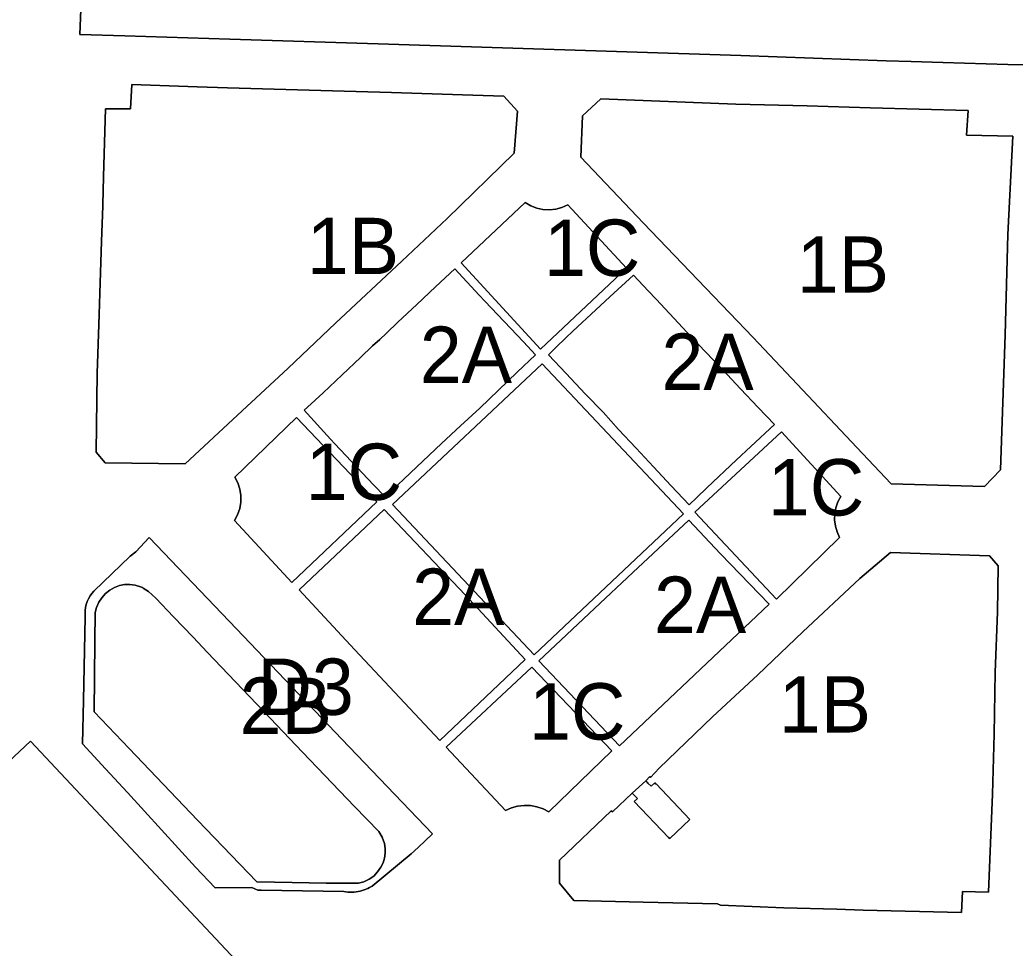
# Model space of a CAD drawing. Extents: x 598968 to 613553, y 4409678 to 4430833.
# Drawn here: x 607397.8 to 607609.6, y 4415075.5 to 4415273.1 of the extents above; entities that cross this region are included whole.
import ezdxf

# ---------------------------------------------------------------- set-up
doc = ezdxf.new("R2010")
doc.units = 0
for name, color, linetype in [('1', 7, 'Continuous'), ('ZONA 1B. Illes de cases extensives - ANNEX III C', 7, 'Continuous'), ('ZONA 1C. Cases aïllades centrals - ANNEX III C', 7, 'Continuous'), ('ZONA 2A. Fileres de cases - ANNEX III C', 7, 'Continuous'), ('ZONA 2B. Blocs aïllats - ANNEX III C', 7, 'Continuous'), ('ZONES URBANES. Espai lliure privat', 7, 'Continuous')]:
    doc.layers.add(name, color=color, linetype=linetype)

msp = doc.modelspace()

# ---------------------------------------------------------------- linework, layer by layer
at = {"layer": '1'}
for points in [[(607611.3336, 4415263.5804), (607608.0558, 4415263.6576), (607594.2184, 4415264.0432), (607587.4797, 4415264.2428), (607582.1741, 4415264.3951), (607551.2448, 4415265.534), (607474.0118, 4415268.0475), (607442.4766, 4415269.0382), (607420.1369, 4415269.7206), (607410.5229, 4415270.0186), (607410.898, 4415278.9685)], [(607410.898, 4415278.9685), (607410.5229, 4415270.0186), (607420.1369, 4415269.7206), (607442.4766, 4415269.0382), (607474.0118, 4415268.0475), (607551.2448, 4415265.534), (607582.1741, 4415264.3951), (607587.4797, 4415264.2428), (607594.2184, 4415264.0432), (607608.0558, 4415263.6576), (607611.3336, 4415263.5804), (607622.943, 4415263.3067), (607622.3131, 4415255.9868), (607622.8407, 4415255.9718), (607622.8617, 4415255.9712), (607647.4966, 4415255.2678), (607658.7094, 4415254.9477), (607666.8208, 4415254.7342), (607667.1204, 4415264.2254), (607667.3182, 4415270.4899), (607667.4999, 4415276.2469)]]:
    msp.add_lwpolyline(points, dxfattribs=at)
for points in [[(607435.5198, 4415258.8828), (607441.9896, 4415258.6528), (607441.9898, 4415258.662), (607464.3096, 4415257.9884), (607476.8744, 4415257.6636), (607492.0193, 4415257.1889), (607500.7892, 4415256.919), (607503.7091, 4415253.6591), (607503.0192, 4415244.7492), (607488.7344, 4415230.8591), (607479.0696, 4415221.769), (607464.9298, 4415208.5289), (607454.8863, 4415199.0005), (607444.13, 4415188.9488), (607432.9602, 4415178.6187), (607415.9204, 4415178.8384), (607414.0304, 4415181.1083), (607414.1503, 4415192.2882), (607414.2603, 4415197.9181), (607414.3703, 4415201.9881), (607414.6403, 4415210.378), (607414.7702, 4415214.9479), (607415.1202, 4415225.9578), (607415.4202, 4415233.5277), (607415.4201, 4415233.72), (607415.5901, 4415239.7577), (607415.9901, 4415254.2175), (607421.3, 4415254.1676), (607421.61, 4415259.3576)], [(607606.4782, 4415177.3419), (607603.0882, 4415173.7619), (607583.2085, 4415174.3515), (607575.9385, 4415182.0613), (607563.2186, 4415195.5609), (607553.8687, 4415205.4906), (607543.8062, 4415215.9717), (607530.4289, 4415229.8999), (607517.189, 4415243.8795), (607517.509, 4415252.7094), (607521.4473, 4415256.2991), (607550.1886, 4415255.1605), (607565.3184, 4415254.8602), (607578.7682, 4415254.4205), (607599.628, 4415253.8009), (607599.258, 4415248.6009), (607609.1079, 4415248.4011), (607608.088, 4415227.4213), (607607.4681, 4415206.0316)], [(607509.1168, 4415232.7569), (607510.4761, 4415232.6832), (607511.8302, 4415232.8239), (607513.1454, 4415233.1756), (607514.3891, 4415233.7296), (607526.919, 4415220.2299), (607508.6193, 4415202.9998), (607491.7215, 4415221.403), (607505.3401, 4415234.2203), (607506.5165, 4415233.5351), (607507.7859, 4415233.0432)], [(607479.5897, 4415175.3996), (607475.5098, 4415171.5396), (607473.0104, 4415174.1262), (607464.8035, 4415182.8902), (607463.9139, 4415183.8399), (607458.2598, 4415189.999), (607459.7899, 4415191.389), (607462.2999, 4415193.7291), (607466.3698, 4415197.5784), (607470.2497, 4415201.2491), (607472.8569, 4415203.7032), (607474.3648, 4415205.0853), (607475.8096, 4415206.4292), (607478.2496, 4415208.7492), (607482.2595, 4415212.5342), (607486.2695, 4415216.2792), (607490.3492, 4415220.1078), (607495.5594, 4415214.5294), (607496.7566, 4415213.2634), (607504.9993, 4415204.5397), (607507.5393, 4415201.8098), (607503.6393, 4415198.0898), (607499.6494, 4415194.2697), (607495.6595, 4415190.4697), (607491.5495, 4415186.6897), (607487.5396, 4415182.8996), (607483.5596, 4415179.1496)], [(607541.8343, 4415171.4398), (607540.199, 4415169.8908), (607536.419, 4415173.9207), (607532.6291, 4415177.9505), (607528.9191, 4415181.9204), (607525.1691, 4415185.9103), (607521.9292, 4415189.5902), (607518.0711, 4415193.4984), (607514.0292, 4415197.81), (607510.2692, 4415201.8198), (607511.8424, 4415203.3382), (607513.9992, 4415205.4199), (607515.5006, 4415206.8299), (607520.3791, 4415211.4099), (607523.3489, 4415214.1858), (607528.359, 4415218.78), (607531.5082, 4415215.4278), (607533.1898, 4415213.6393), (607536.0656, 4415210.5756), (607539.8309, 4415206.5799), (607543.6288, 4415202.5355), (607547.3711, 4415198.5879), (607551.1564, 4415194.5837), (607554.9461, 4415190.5909), (607558.3987, 4415186.9509), (607553.358, 4415182.2713), (607550.3244, 4415179.4216), (607543.9889, 4415173.4808)], [(607538.9907, 4415167.9746), (607507.2504, 4415137.9118), (607477.0567, 4415169.912), (607508.9508, 4415199.9041)], [(607538.9907, 4415167.9746), (607508.9508, 4415199.9041), (607477.0567, 4415169.912), (607507.2504, 4415137.9118)], [(607473.7531, 4415170.5019), (607455.66, 4415153.3594), (607443.4701, 4415166.499), (607444.1285, 4415167.7325), (607444.5812, 4415169.0554), (607444.8165, 4415170.4337), (607444.8285, 4415171.8318), (607444.6169, 4415173.2139), (607444.1871, 4415174.5443), (607443.55, 4415175.7889), (607456.6498, 4415188.449)], [(607572.2586, 4415162.9014), (607558.7888, 4415149.8113), (607541.449, 4415168.2808), (607559.8687, 4415185.391), (607572.5186, 4415171.6613), (607571.902, 4415170.5025), (607571.4694, 4415169.2632), (607571.2308, 4415167.9724), (607571.1919, 4415166.6603), (607571.3535, 4415165.3576), (607571.7118, 4415164.0948)], [(607505.3095, 4415136.9205), (607487.1555, 4415119.7133), (607469.02, 4415139.0698), (607457.2061, 4415151.7545), (607475.2898, 4415168.8596), (607492.5653, 4415150.7299)], [(607557.2589, 4415148.7113), (607525.3938, 4415118.5673), (607508.2295, 4415136.6506), (607520.0993, 4415147.7807), (607528.2592, 4415155.4307), (607540.169, 4415166.6108), (607546.899, 4415159.421)], [(607425.3178, 4415162.8913), (607443.8875, 4415143.4525), (607449.7074, 4415137.3529), (607458.7472, 4415127.8935), (607460.6173, 4415125.9336), (607466.3173, 4415119.9739), (607485.5769, 4415099.8051), (607482.5371, 4415096.9151), (607481.0671, 4415095.5251), (607472.7273, 4415088.6449), (607472.2273, 4415088.3649), (607471.8373, 4415088.1749), (607471.0274, 4415087.8549), (607470.6174, 4415087.7249), (607470.1974, 4415087.6149), (607469.7674, 4415087.5249), (607469.3374, 4415087.4548), (607468.9074, 4415087.4148), (607468.4775, 4415087.3848), (607468.0375, 4415087.3847), (607467.6075, 4415087.4047), (607467.1775, 4415087.4447), (607466.7475, 4415087.5147), (607449.1478, 4415087.8341), (607448.4278, 4415087.8441), (607447.1278, 4415088.3539), (607439.358, 4415088.3437), (607435.1481, 4415092.6835), (607420.6684, 4415108.5925), (607416.0284, 4415113.6423), (607411.1085, 4415118.9819), (607411.3184, 4415128.1917), (607411.7082, 4415146.0313), (607411.6482, 4415146.6913), (607411.6682, 4415147.3513), (607411.7482, 4415148.0113), (607411.8982, 4415148.6513), (607412.1082, 4415149.2812), (607412.3782, 4415149.8812), (607412.7082, 4415150.4612), (607413.0882, 4415150.9912), (607413.5282, 4415151.4912), (607421.238, 4415158.9313), (607422.4279, 4415159.8613)], [(607530.99, 4415111.1115), (607531.8696, 4415111.9911), (607532.0193, 4415111.8413), (607533.8793, 4415113.7814), (607545.1791, 4415124.7614), (607554.829, 4415133.7015), (607564.3989, 4415142.829), (607576.5218, 4415154.1789), (607583.0785, 4415159.7017), (607604.1483, 4415159.0421), (607606.0183, 4415156.9021), (607605.8383, 4415146.9922), (607605.3627, 4415134.23), (607605.1584, 4415121.0626), (607604.7984, 4415108.2927), (607603.9585, 4415087.363), (607598.3975, 4415087.5292), (607598.2086, 4415083.0529), (607577.2589, 4415083.5725), (607571.6689, 4415083.7424), (607560.3891, 4415084.0722), (607546.8892, 4415084.6019), (607546.2692, 4415084.8919), (607530.4294, 4415085.2916), (607515.7096, 4415085.6313), (607512.6196, 4415089.3312), (607512.6596, 4415094.1712), (607523.6594, 4415104.7013), (607523.8794, 4415104.4713), (607528.1094, 4415108.5013)], [(607523.7816, 4415117.4735), (607510.3696, 4415104.481), (607509.1421, 4415105.1196), (607507.833, 4415105.5673), (607506.4716, 4415105.8141), (607505.0886, 4415105.8545), (607503.7152, 4415105.6874), (607502.3822, 4415105.3168), (607501.1197, 4415104.7509), (607488.4998, 4415118.2805), (607506.7795, 4415135.2906)], [(607406.2436, 4415028.3837), (607357.7665, 4415079.882), (607400.0659, 4415119.5323), (607448.0291, 4415068.3834), (607494.246, 4415066.8294), (607500.435, 4415062.8748), (607499.825, 4415051.5949), (607498.0651, 4415043.685), (607491.9652, 4415032.845), (607490.0452, 4415030.475), (607482.0353, 4415016.935), (607480.3354, 4415012.755), (607477.1754, 4415002.7051), (607475.9355, 4414997.5151), (607474.8055, 4414990.8552), (607474.0155, 4414988.7052), (607472.5456, 4414987.3552), (607471.0256, 4414986.6852), (607467.1856, 4414986.4151), (607404.8763, 4414988.4539)], [(607448.0291, 4415068.3834), (607400.0659, 4415119.5323), (607357.7665, 4415079.882), (607406.2436, 4415028.3837), (607406.4361, 4415034.0034), (607442.4385, 4415068.5714)], [(607528.1094, 4415108.5013), (607529.2338, 4415107.3272), (607528.5594, 4415106.6813), (607535.8093, 4415099.0516), (607536.1044, 4415098.7951), (607540.3843, 4415102.8651), (607533.1844, 4415110.4349), (607533.1576, 4415110.4091), (607532.8893, 4415110.6914), (607532.1327, 4415109.9639), (607532.1093, 4415109.9414), (607531.4569, 4415110.6234), (607531.2587, 4415110.8306), (607530.99, 4415111.1115)]]:
    msp.add_lwpolyline(points, close=True, dxfattribs=at)
at = {"layer": 'ZONA 1B. Illes de cases extensives - ANNEX III C'}
for points in [[(607435.5198, 4415258.8828), (607421.61, 4415259.3576), (607421.3, 4415254.1676), (607415.9901, 4415254.2175), (607415.5901, 4415239.7577), (607415.4201, 4415233.72), (607415.4202, 4415233.5277), (607415.1202, 4415225.9578), (607414.7702, 4415214.9479), (607414.6403, 4415210.378), (607414.3703, 4415201.9881), (607414.2603, 4415197.9181), (607414.1503, 4415192.2882), (607414.0304, 4415181.1083), (607415.9204, 4415178.8384), (607432.9602, 4415178.6187), (607444.13, 4415188.9488), (607454.8863, 4415199.0005), (607464.9298, 4415208.5289), (607479.0696, 4415221.769), (607488.7344, 4415230.8591), (607503.0192, 4415244.7492), (607503.7091, 4415253.6591), (607500.7892, 4415256.919), (607492.0193, 4415257.1889), (607476.8744, 4415257.6636), (607464.3096, 4415257.9884), (607441.9898, 4415258.662), (607441.9896, 4415258.6528)], [(607606.4782, 4415177.3419), (607607.4681, 4415206.0316), (607608.088, 4415227.4213), (607609.1079, 4415248.4011), (607599.258, 4415248.6009), (607599.628, 4415253.8009), (607578.7682, 4415254.4205), (607565.3184, 4415254.8602), (607550.1886, 4415255.1605), (607521.4473, 4415256.2991), (607517.509, 4415252.7094), (607517.189, 4415243.8795), (607530.4289, 4415229.8999), (607543.8062, 4415215.9717), (607553.8687, 4415205.4906), (607563.2186, 4415195.5609), (607575.9385, 4415182.0613), (607583.2085, 4415174.3515), (607603.0882, 4415173.7619)], [(607528.1094, 4415108.5013), (607523.8794, 4415104.4713), (607523.6594, 4415104.7013), (607512.6596, 4415094.1712), (607512.6196, 4415089.3312), (607515.7096, 4415085.6313), (607530.4294, 4415085.2916), (607546.2692, 4415084.8919), (607546.8892, 4415084.6019), (607560.3891, 4415084.0722), (607571.6689, 4415083.7424), (607577.2589, 4415083.5725), (607598.2086, 4415083.0529), (607598.3975, 4415087.5292), (607603.9585, 4415087.363), (607604.7984, 4415108.2927), (607605.1584, 4415121.0626), (607605.3627, 4415134.23), (607605.8383, 4415146.9922), (607606.0183, 4415156.9021), (607604.1483, 4415159.0421), (607583.0785, 4415159.7017), (607576.5218, 4415154.1789), (607564.3989, 4415142.829), (607554.829, 4415133.7015), (607545.1791, 4415124.7614), (607533.8793, 4415113.7814), (607532.0193, 4415111.8413), (607531.8696, 4415111.9911), (607530.99, 4415111.1115), (607531.2587, 4415110.8306), (607531.4569, 4415110.6234), (607532.1093, 4415109.9414), (607532.1327, 4415109.9639), (607532.8893, 4415110.6914), (607533.1576, 4415110.4091), (607533.1844, 4415110.4349), (607540.3843, 4415102.8651), (607536.1044, 4415098.7951), (607535.8093, 4415099.0516), (607528.5594, 4415106.6813), (607529.2338, 4415107.3272)]]:
    msp.add_lwpolyline(points, close=True, dxfattribs=at)
at = {"layer": 'ZONA 1C. Cases aïllades centrals - ANNEX III C'}
for points in [[(607509.1168, 4415232.7569), (607507.7859, 4415233.0432), (607506.5165, 4415233.5351), (607505.3401, 4415234.2203), (607491.7215, 4415221.403), (607508.6193, 4415202.9998), (607526.919, 4415220.2299), (607514.3891, 4415233.7296), (607513.1454, 4415233.1756), (607511.8302, 4415232.8239), (607510.4761, 4415232.6832)], [(607473.7531, 4415170.5019), (607456.6498, 4415188.449), (607443.55, 4415175.7889), (607444.1871, 4415174.5443), (607444.6169, 4415173.2139), (607444.8285, 4415171.8318), (607444.8165, 4415170.4337), (607444.5812, 4415169.0554), (607444.1285, 4415167.7325), (607443.4701, 4415166.499), (607455.66, 4415153.3594)], [(607572.2586, 4415162.9014), (607571.7118, 4415164.0948), (607571.3535, 4415165.3576), (607571.1919, 4415166.6603), (607571.2308, 4415167.9724), (607571.4694, 4415169.2632), (607571.902, 4415170.5025), (607572.5186, 4415171.6613), (607559.8687, 4415185.391), (607541.449, 4415168.2808), (607558.7888, 4415149.8113)], [(607523.7816, 4415117.4735), (607506.7795, 4415135.2906), (607488.4998, 4415118.2805), (607501.1197, 4415104.7509), (607502.3822, 4415105.3168), (607503.7152, 4415105.6874), (607505.0886, 4415105.8545), (607506.4716, 4415105.8141), (607507.833, 4415105.5673), (607509.1421, 4415105.1196), (607510.3696, 4415104.481)]]:
    msp.add_lwpolyline(points, close=True, dxfattribs=at)
at = {"layer": 'ZONA 2A. Fileres de cases - ANNEX III C'}
for points in [[(607479.5897, 4415175.3996), (607483.5596, 4415179.1496), (607487.5396, 4415182.8996), (607491.5495, 4415186.6897), (607495.6595, 4415190.4697), (607499.6494, 4415194.2697), (607503.6393, 4415198.0898), (607507.5393, 4415201.8098), (607504.9993, 4415204.5397), (607496.7566, 4415213.2634), (607495.5594, 4415214.5294), (607490.3492, 4415220.1078), (607486.2695, 4415216.2792), (607482.2595, 4415212.5342), (607478.2496, 4415208.7492), (607475.8096, 4415206.4292), (607474.3648, 4415205.0853), (607472.8569, 4415203.7032), (607470.2497, 4415201.2491), (607466.3698, 4415197.5784), (607462.2999, 4415193.7291), (607459.7899, 4415191.389), (607458.2598, 4415189.999), (607463.9139, 4415183.8399), (607464.8035, 4415182.8902), (607473.0104, 4415174.1262), (607475.5098, 4415171.5396)], [(607541.8343, 4415171.4398), (607543.9889, 4415173.4808), (607550.3244, 4415179.4216), (607553.358, 4415182.2713), (607558.3987, 4415186.9509), (607554.9461, 4415190.5909), (607551.1564, 4415194.5837), (607547.3711, 4415198.5879), (607543.6288, 4415202.5355), (607539.8309, 4415206.5799), (607536.0656, 4415210.5756), (607533.1898, 4415213.6393), (607531.5082, 4415215.4278), (607528.359, 4415218.78), (607523.3489, 4415214.1858), (607520.3791, 4415211.4099), (607515.5006, 4415206.8299), (607513.9992, 4415205.4199), (607511.8424, 4415203.3382), (607510.2692, 4415201.8198), (607514.0292, 4415197.81), (607518.0711, 4415193.4984), (607521.9292, 4415189.5902), (607525.1691, 4415185.9103), (607528.9191, 4415181.9204), (607532.6291, 4415177.9505), (607536.419, 4415173.9207), (607540.199, 4415169.8908)], [(607505.3095, 4415136.9205), (607492.5653, 4415150.7299), (607475.2898, 4415168.8596), (607457.2061, 4415151.7545), (607469.02, 4415139.0698), (607487.1555, 4415119.7133)], [(607557.2589, 4415148.7113), (607546.899, 4415159.421), (607540.169, 4415166.6108), (607528.2592, 4415155.4307), (607520.0993, 4415147.7807), (607508.2295, 4415136.6506), (607525.3938, 4415118.5673)]]:
    msp.add_lwpolyline(points, close=True, dxfattribs=at)
at = {"layer": 'ZONA 2B. Blocs aïllats - ANNEX III C'}
msp.add_lwpolyline([(607469.8401, 4415089.2805), (607471.0049, 4415089.6049), (607472.0964, 4415090.1253), (607473.0817, 4415090.8262), (607473.9315, 4415091.6865), (607474.6201, 4415092.6805), (607475.0715, 4415093.6287), (607475.3772, 4415094.6333), (607475.5306, 4415095.6722), (607475.5282, 4415096.7224), (607475.37, 4415097.7605), (607474.8551, 4415099.0782), (607474.16, 4415100.3104), (607468.9801, 4415105.6403), (607457.9301, 4415117.2199), (607449.6701, 4415125.8597), (607437.6102, 4415138.5092), (607434.631, 4415141.6792), (607430.4703, 4415145.989), (607426.7003, 4415149.9589), (607425.1903, 4415151.3989), (607424.0354, 4415152.1288), (607423.8484, 4415152.2655), (607423.6416, 4415152.3698), (607423.4204, 4415152.4388), (607422.3354, 4415152.7649), (607421.2119, 4415152.9119), (607420.0795, 4415152.876), (607418.9677, 4415152.6579), (607417.9054, 4415152.2637), (607416.8927, 4415151.6863), (607415.9852, 4415150.9546), (607415.2062, 4415150.0873), (607414.5756, 4415149.1068), (607414.1098, 4415148.0381), (607413.8205, 4415146.9087), (607413.7205, 4415140.7788), (607413.5906, 4415125.759), (607421.0205, 4415117.9992), (607435.6204, 4415102.7497), (607448.1903, 4415089.6201), (607455.7412, 4415089.484), (607462.9502, 4415089.2803)], close=True, dxfattribs=at)
at = {"layer": 'ZONES URBANES. Espai lliure privat'}
for points in [[(607425.3178, 4415162.8913), (607422.4279, 4415159.8613), (607421.238, 4415158.9313), (607413.5282, 4415151.4912), (607413.0882, 4415150.9912), (607412.7082, 4415150.4612), (607412.3782, 4415149.8812), (607412.1082, 4415149.2812), (607411.8982, 4415148.6513), (607411.7482, 4415148.0113), (607411.6682, 4415147.3513), (607411.6482, 4415146.6913), (607411.7082, 4415146.0313), (607411.3184, 4415128.1917), (607411.1085, 4415118.9819), (607416.0284, 4415113.6423), (607420.6684, 4415108.5925), (607435.1481, 4415092.6835), (607439.358, 4415088.3437), (607447.1278, 4415088.3539), (607448.4278, 4415087.8441), (607449.1478, 4415087.8341), (607466.7475, 4415087.5147), (607467.1775, 4415087.4447), (607467.6075, 4415087.4047), (607468.0375, 4415087.3847), (607468.4775, 4415087.3848), (607468.9074, 4415087.4148), (607469.3374, 4415087.4548), (607469.7674, 4415087.5249), (607470.1974, 4415087.6149), (607470.6174, 4415087.7249), (607471.0274, 4415087.8549), (607471.8373, 4415088.1749), (607472.2273, 4415088.3649), (607472.7273, 4415088.6449), (607481.0671, 4415095.5251), (607482.5371, 4415096.9151), (607485.5769, 4415099.8051), (607466.3173, 4415119.9739), (607460.6173, 4415125.9336), (607458.7472, 4415127.8935), (607449.7074, 4415137.3529), (607443.8875, 4415143.4525)], [(607469.8401, 4415089.2805), (607462.9502, 4415089.2803), (607455.7412, 4415089.484), (607448.1903, 4415089.6201), (607435.6204, 4415102.7497), (607421.0205, 4415117.9992), (607413.5906, 4415125.759), (607413.7205, 4415140.7788), (607413.8205, 4415146.9087), (607414.1098, 4415148.0381), (607414.5756, 4415149.1068), (607415.2062, 4415150.0873), (607415.9852, 4415150.9546), (607416.8927, 4415151.6863), (607417.9054, 4415152.2637), (607418.9677, 4415152.6579), (607420.0795, 4415152.876), (607421.2119, 4415152.9119), (607422.3354, 4415152.7649), (607423.4204, 4415152.4388), (607423.6416, 4415152.3698), (607423.8484, 4415152.2655), (607424.0354, 4415152.1288), (607425.1903, 4415151.3989), (607426.7003, 4415149.9589), (607430.4703, 4415145.989), (607434.631, 4415141.6792), (607437.6102, 4415138.5092), (607449.6701, 4415125.8597), (607457.9301, 4415117.2199), (607468.9801, 4415105.6403), (607474.16, 4415100.3104), (607474.8551, 4415099.0782), (607475.37, 4415097.7605), (607475.5282, 4415096.7224), (607475.5306, 4415095.6722), (607475.3772, 4415094.6333), (607475.0715, 4415093.6287), (607474.6201, 4415092.6805), (607473.9315, 4415091.6865), (607473.0817, 4415090.8262), (607472.0964, 4415090.1253), (607471.0049, 4415089.6049)]]:
    msp.add_lwpolyline(points, close=True, dxfattribs=at)

# ---------------------------------------------------------------- texts
at = {"layer": 'ZONA 1B. Illes de cases extensives - ANNEX III C'}
for p in [(607458.8697, 4415218.9881), (607563.1485, 4415215.0305), (607559.3189, 4415121.3773)]:
    msp.add_text('1B', height=12, dxfattribs=at).set_placement(p)
at = {"layer": 'ZONA 1C. Cases aïllades centrals - ANNEX III C'}
for p in [(607509.3202, 4415218.6101), (607458.6116, 4415170.9042), (607556.9838, 4415167.6012), (607506.1407, 4415119.8858)]:
    msp.add_text('1C', height=12, dxfattribs=at).set_placement(p)
at = {"layer": 'ZONA 2A. Fileres de cases - ANNEX III C'}
for p in [(607482.8996, 4415195.8237), (607534.3339, 4415194.3354), (607481.2578, 4415144.2865), (607532.7442, 4415142.589)]:
    msp.add_text('2A', height=12, dxfattribs=at).set_placement(p)
at = {"layer": 'ZONA 2B. Blocs aïllats - ANNEX III C'}
msp.add_text('2B', height=12, dxfattribs=at).set_placement((607444.5606, 4415121.0961))
at = {"layer": 'ZONES URBANES. Espai lliure privat'}
msp.add_text('D3', height=12, dxfattribs=at).set_placement((607448.3427, 4415125.138))

doc.saveas('drawing.dxf')
